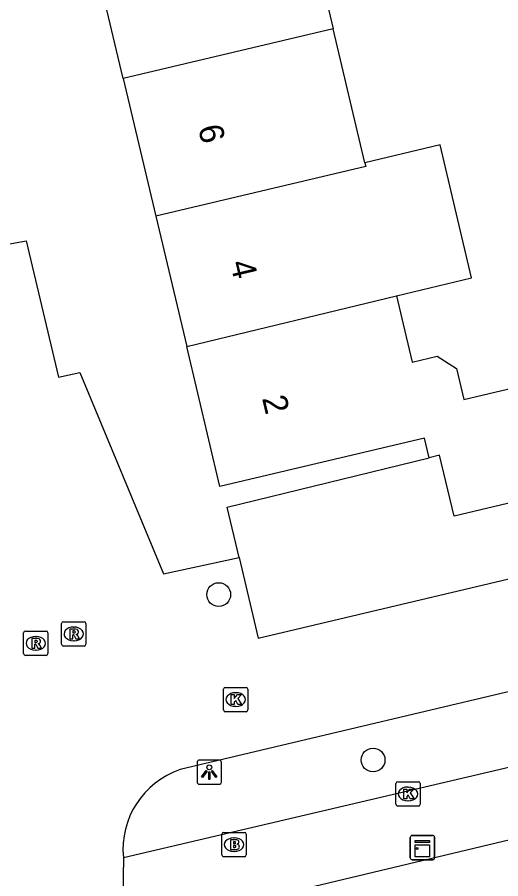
# Model space of a CAD drawing. Extents: x 158038 to 159242, y 380133 to 381214.
# Drawn here: x 158523.03 to 158542.9, y 381056.48 to 381091.9 of the extents above; entities that cross this region are included whole.
import ezdxf

# ---------------------------------------------------------------- set-up
doc = ezdxf.new("R2010")
doc.units = 0
for name, color, linetype in [('IMGEO_Boom', 7, 'Continuous'), ('IMGEO_Brandkraan', 7, 'Continuous'), ('IMGEO_Kast', 7, 'Continuous'), ('IMGEO_Kolk', 7, 'Continuous'), ('IMGEO_Lichtpunt', 7, 'Continuous'), ('IMGEO_Pand', 7, 'Continuous'), ('IMGEO_Pand_nummerreeks', 7, 'Continuous'), ('IMGEO_Parkeervlak_open', 7, 'Continuous'), ('IMGEO_Rioolput', 7, 'Continuous'), ('IMGEO_Voetpad_open', 7, 'Continuous')]:
    doc.layers.add(name, color=color, linetype=linetype)

msp = doc.modelspace()

# ---------------------------------------------------------------- linework, layer by layer
at = {"layer": 'IMGEO_Boom'}
for centre in [(158531.311, 381068.166), (158537.652, 381061.367)]:
    msp.add_circle(centre, 0.489, dxfattribs=at)
at = {"layer": 'IMGEO_Brandkraan'}
for p, q in [((158531.442, 381057.464), (158531.442, 381058.316)), ((158531.517, 381058.39), (158532.369, 381058.39)), ((158532.443, 381058.316), (158532.443, 381057.464)), ((158531.93, 381058.17), (158531.955, 381058.17)), ((158531.953, 381057.61), (158531.928, 381057.61)), ((158532.369, 381057.39), (158531.517, 381057.39))]:
    msp.add_line(p, q, dxfattribs=at)
for points in [[(158531.442, 381057.464), (158531.442, 381058.316)], [(158531.517, 381058.39), (158532.369, 381058.39)], [(158532.443, 381058.316), (158532.443, 381057.464)], [(158531.79, 381058.09), (158531.79, 381057.69), (158532.003, 381057.69)], [(158532.021, 381058.09), (158531.79, 381058.09)], [(158531.969, 381058.009), (158531.915, 381058.009), (158531.915, 381057.933)], [(158531.915, 381057.933), (158531.968, 381057.933)], [(158531.977, 381057.857), (158531.915, 381057.857), (158531.915, 381057.776)], [(158531.915, 381057.776), (158531.977, 381057.776)], [(158532.369, 381057.39), (158531.517, 381057.39)]]:
    msp.add_lwpolyline(points, dxfattribs=at)
for centre, radius, start, end in [((158531.519, 381058.314), 0.0765, 91.552, 178.448), ((158531.519, 381058.314), 0.0765, 91.552, 178.448), ((158532.367, 381058.314), 0.0765, 1.552, 88.448), ((158532.367, 381058.314), 0.0765, 1.552, 88.448), ((158531.97, 381057.971), 0.0379, 267.8285, 90.9355), ((158532.025, 381057.945), 0.145, 59.4692, 91.5367), ((158532.05, 381057.992), 0.0922, 285.5137, 58.1501), ((158532.055, 381057.8), 0.105, 301.3115, 78.989), ((158531.978, 381057.816), 0.0404, 269.8759, 90.5077), ((158532.009, 381057.941), 0.251, 268.6676, 293.5347), ((158531.519, 381057.466), 0.0765, 181.552, 268.448), ((158531.519, 381057.466), 0.0765, 181.552, 268.448), ((158532.367, 381057.466), 0.0765, 271.552, 358.448), ((158532.367, 381057.466), 0.0765, 271.552, 358.448)]:
    msp.add_arc(centre, radius, start, end, dxfattribs=at)
for centre, major_axis, ratio, start_param, end_param in [((158531.929, 381057.89), (-0.387, 0.002), 0.722429, 4.712389, 7.853982), ((158531.954, 381057.89), (-0.39, 0.002), 0.717154, 1.570796, 4.712389)]:
    msp.add_ellipse(centre, major_axis=major_axis, ratio=ratio, start_param=start_param, end_param=end_param, dxfattribs=at)
at = {"layer": 'IMGEO_Kast'}
for p, q in [((158539.257, 381058.267), (158540.098, 381058.267)), ((158540.098, 381058.267), (158539.257, 381058.267)), ((158539.182, 381057.342), (158539.182, 381058.183)), ((158539.182, 381058.183), (158539.182, 381057.342)), ((158540.182, 381058.192), (158540.182, 381057.351)), ((158540.182, 381057.351), (158540.182, 381058.192)), ((158540.107, 381057.267), (158539.266, 381057.267)), ((158539.266, 381057.267), (158540.107, 381057.267))]:
    msp.add_line(p, q, dxfattribs=at)
for points in [[(158539.377, 381058.057), (158539.977, 381058.057), (158539.977, 381057.972), (158539.377, 381057.972), (158539.377, 381058.057)], [(158539.377, 381057.882), (158539.977, 381057.882), (158539.977, 381057.393), (158539.377, 381057.393), (158539.377, 381057.882)]]:
    msp.add_lwpolyline(points, dxfattribs=at)
msp.add_circle((158539.461, 381057.731), 0.0377, dxfattribs=at)
for centre, start, end in [((158539.26, 381058.189), 92.4484, 184.2845), ((158539.26, 381058.189), 92.4484, 184.2845), ((158540.104, 381058.189), 2.4484, 94.2845), ((158540.104, 381058.189), 2.4484, 94.2845), ((158539.26, 381057.345), 182.4484, 274.2845), ((158539.26, 381057.345), 182.4484, 274.2845), ((158540.104, 381057.345), 272.4484, 4.2845), ((158540.104, 381057.345), 272.4484, 4.2845)]:
    msp.add_arc(centre, 0.0779, start, end, dxfattribs=at)
at = {"layer": 'IMGEO_Kolk'}
for p, q in [((158531.508, 381063.427), (158531.508, 381064.279)), ((158531.583, 381064.353), (158532.435, 381064.353)), ((158532.509, 381064.279), (158532.509, 381063.427)), ((158531.996, 381064.133), (158532.021, 381064.133)), ((158532.019, 381063.573), (158531.994, 381063.573)), ((158532.435, 381063.353), (158531.583, 381063.353)), ((158538.59, 381059.548), (158538.59, 381060.4)), ((158538.665, 381060.474), (158539.517, 381060.474)), ((158539.591, 381060.4), (158539.591, 381059.548)), ((158539.078, 381060.254), (158539.103, 381060.254)), ((158539.101, 381059.694), (158539.076, 381059.694)), ((158539.517, 381059.474), (158538.665, 381059.474))]:
    msp.add_line(p, q, dxfattribs=at)
for points in [[(158531.508, 381063.427), (158531.508, 381064.279)], [(158531.583, 381064.353), (158532.435, 381064.353)], [(158532.509, 381064.279), (158532.509, 381063.427)], [(158531.829, 381064.053), (158531.952, 381064.053), (158531.952, 381063.902), (158532.082, 381064.053), (158532.246, 381064.053), (158532.1, 381063.902), (158532.253, 381063.653), (158532.101, 381063.653), (158532.016, 381063.817), (158531.952, 381063.75), (158531.952, 381063.653), (158531.829, 381063.653), (158531.829, 381064.053)], [(158532.435, 381063.353), (158531.583, 381063.353)], [(158538.59, 381059.548), (158538.59, 381060.4)], [(158538.665, 381060.474), (158539.517, 381060.474)], [(158539.591, 381060.4), (158539.591, 381059.548)], [(158538.911, 381060.174), (158539.034, 381060.174), (158539.034, 381060.023), (158539.164, 381060.174), (158539.328, 381060.174), (158539.182, 381060.023), (158539.335, 381059.774), (158539.183, 381059.774), (158539.098, 381059.938), (158539.034, 381059.871), (158539.034, 381059.774), (158538.911, 381059.774), (158538.911, 381060.174)], [(158539.517, 381059.474), (158538.665, 381059.474)]]:
    msp.add_lwpolyline(points, dxfattribs=at)
for centre, start, end in [((158531.585, 381064.277), 91.552, 178.448), ((158531.585, 381064.277), 91.552, 178.448), ((158532.433, 381064.277), 1.552, 88.448), ((158532.433, 381064.277), 1.552, 88.448), ((158531.585, 381063.429), 181.552, 268.448), ((158531.585, 381063.429), 181.552, 268.448), ((158532.433, 381063.429), 271.552, 358.448), ((158532.433, 381063.429), 271.552, 358.448), ((158538.667, 381060.398), 91.552, 178.448), ((158538.667, 381060.398), 91.552, 178.448), ((158539.515, 381060.398), 1.552, 88.448), ((158539.515, 381060.398), 1.552, 88.448), ((158538.667, 381059.55), 181.552, 268.448), ((158538.667, 381059.55), 181.552, 268.448), ((158539.515, 381059.55), 271.552, 358.448), ((158539.515, 381059.55), 271.552, 358.448)]:
    msp.add_arc(centre, 0.0765, start, end, dxfattribs=at)
for centre, major_axis, ratio, start_param, end_param in [((158531.995, 381063.853), (-0.387, 0.002), 0.722429, 4.712389, 7.853982), ((158532.02, 381063.853), (-0.39, 0.002), 0.717154, 1.570796, 4.712389), ((158539.077, 381059.974), (-0.387, 0.002), 0.722429, 4.712389, 7.853982), ((158539.102, 381059.974), (-0.39, 0.002), 0.717154, 1.570796, 4.712389)]:
    msp.add_ellipse(centre, major_axis=major_axis, ratio=ratio, start_param=start_param, end_param=end_param, dxfattribs=at)
at = {"layer": 'IMGEO_Lichtpunt'}
for p, q in [((158530.424, 381061.269), (158530.424, 381060.462)), ((158530.424, 381061.269), (158530.424, 381060.462)), ((158531.326, 381061.364), (158530.518, 381061.364)), ((158531.326, 381061.364), (158530.518, 381061.364)), ((158531.42, 381060.462), (158531.42, 381061.269)), ((158531.42, 381060.462), (158531.42, 381061.269)), ((158530.518, 381060.368), (158531.326, 381060.368)), ((158530.518, 381060.368), (158531.326, 381060.368))]:
    msp.add_line(p, q, dxfattribs=at)
for points in [[(158530.798, 381060.933), (158530.837, 381060.905), (158530.649, 381060.643), (158530.611, 381060.67), (158530.798, 381060.933)], [(158530.9, 381060.885), (158530.947, 381060.885), (158530.947, 381060.563), (158530.9, 381060.563), (158530.9, 381060.885)], [(158531.01, 381060.905), (158531.048, 381060.932), (158531.235, 381060.67), (158531.196, 381060.642), (158531.01, 381060.905)]]:
    msp.add_lwpolyline(points, dxfattribs=at)
msp.add_circle((158530.923, 381061.067), 0.0994, dxfattribs=at)
for centre, start, end in [((158530.518, 381061.269), 90, 180), ((158530.518, 381061.269), 90, 180), ((158531.326, 381061.269), 0, 90), ((158531.326, 381061.269), 0, 90), ((158530.518, 381060.462), 180, 270), ((158530.518, 381060.462), 180, 270), ((158531.326, 381060.462), 270, 0), ((158531.326, 381060.462), 270, 360)]:
    msp.add_arc(centre, 0.0946, start, end, dxfattribs=at)
at = {"layer": 'IMGEO_Pand'}
for points in [[(158531.205, 381096.425), (158534.64, 381097.237), (158536.016, 381091.421)], [(158527.39, 381089.381), (158526.446, 381093.375), (158526.093, 381094.866), (158526.045, 381095.067)], [(158536.016, 381091.421), (158527.39, 381089.381)], [(158537.317, 381085.919), (158536.016, 381091.421)], [(158527.39, 381089.381), (158528.73, 381083.718)], [(158538.612, 381080.445), (158541.698, 381081.191), (158540.406, 381086.65), (158537.317, 381085.919)], [(158537.317, 381085.919), (158537.355, 381085.758), (158528.73, 381083.718)], [(158528.73, 381083.718), (158529.997, 381078.361)], [(158529.997, 381078.361), (158538.612, 381080.445)], [(158538.612, 381080.445), (158538.831, 381079.518), (158539.256, 381077.722), (158540.282, 381077.965), (158541.081, 381077.455), (158541.379, 381076.189), (158546.537, 381077.409), (158547.771, 381076.622), (158548.507, 381073.507), (158548.76, 381073.566), (158548.833, 381073.254)], [(158539.958, 381073.794), (158539.766, 381074.601), (158531.357, 381072.612), (158529.997, 381078.361)], [(158548.833, 381073.254), (158540.979, 381071.396), (158540.387, 381073.896), (158539.958, 381073.794)]]:
    msp.add_lwpolyline(points, dxfattribs=at)
at = {"layer": 'IMGEO_Parkeervlak_open'}
msp.add_lwpolyline([(158532.148, 381069.695), (158531.659, 381071.763), (158539.958, 381073.794)], dxfattribs=at)
at = {"layer": 'IMGEO_Rioolput'}
for p, q in [((158524.856, 381066.126), (158524.856, 381066.978)), ((158524.931, 381067.052), (158525.783, 381067.052)), ((158525.344, 381066.832), (158525.369, 381066.832)), ((158525.857, 381066.978), (158525.857, 381066.126)), ((158523.295, 381065.739), (158523.295, 381066.591)), ((158523.37, 381066.665), (158524.222, 381066.665)), ((158523.783, 381066.445), (158523.808, 381066.445)), ((158524.296, 381066.591), (158524.296, 381065.739)), ((158525.783, 381066.052), (158524.931, 381066.052)), ((158525.367, 381066.272), (158525.342, 381066.272)), ((158524.222, 381065.665), (158523.37, 381065.665)), ((158523.806, 381065.885), (158523.781, 381065.885))]:
    msp.add_line(p, q, dxfattribs=at)
for points in [[(158524.856, 381066.126), (158524.856, 381066.978)], [(158524.931, 381067.052), (158525.783, 381067.052)], [(158525.445, 381066.75), (158525.193, 381066.752), (158525.193, 381066.352)], [(158525.857, 381066.978), (158525.857, 381066.126)], [(158523.295, 381065.739), (158523.295, 381066.591)], [(158523.37, 381066.665), (158524.222, 381066.665)], [(158524.296, 381066.591), (158524.296, 381065.739)], [(158525.193, 381066.352), (158525.317, 381066.352), (158525.317, 381066.514), (158525.328, 381066.514)], [(158525.371, 381066.671), (158525.317, 381066.671), (158525.317, 381066.59)], [(158525.317, 381066.59), (158525.369, 381066.59)], [(158525.375, 381066.485), (158525.446, 381066.352), (158525.586, 381066.352), (158525.521, 381066.478)], [(158523.884, 381066.363), (158523.632, 381066.365), (158523.632, 381065.965)], [(158523.632, 381065.965), (158523.756, 381065.965), (158523.756, 381066.127), (158523.767, 381066.127)], [(158523.81, 381066.284), (158523.756, 381066.284), (158523.756, 381066.203)], [(158523.756, 381066.203), (158523.808, 381066.203)], [(158523.814, 381066.098), (158523.885, 381065.965), (158524.025, 381065.965), (158523.96, 381066.091)], [(158525.783, 381066.052), (158524.931, 381066.052)], [(158524.222, 381065.665), (158523.37, 381065.665)]]:
    msp.add_lwpolyline(points, dxfattribs=at)
for centre, radius, start, end in [((158524.933, 381066.976), 0.0765, 91.552, 178.448), ((158524.933, 381066.976), 0.0765, 91.552, 178.448), ((158525.444, 381066.64), 0.109, 350.3612, 89.416), ((158525.781, 381066.976), 0.0765, 1.552, 88.448), ((158525.781, 381066.976), 0.0765, 1.552, 88.448), ((158523.372, 381066.589), 0.0765, 91.552, 178.448), ((158523.372, 381066.589), 0.0765, 91.552, 178.448), ((158524.22, 381066.589), 0.0765, 1.552, 88.448), ((158524.22, 381066.589), 0.0765, 1.552, 88.448), ((158525.327, 381066.461), 0.0533, 26.0293, 88.6989), ((158525.353, 381066.779), 0.19, 274.7715, 282.9687), ((158525.377, 381066.575), 0.0964, 77.0061, 93.1865), ((158525.391, 381066.632), 0.0378, 276.6634, 79.6772), ((158525.442, 381066.64), 0.112, 277.5842, 350.9817), ((158525.426, 381066.425), 0.108, 29.5134, 73.7905), ((158523.766, 381066.074), 0.0533, 26.0293, 88.6989), ((158523.792, 381066.392), 0.19, 274.7715, 282.9687), ((158523.816, 381066.188), 0.0964, 77.0061, 93.1865), ((158523.83, 381066.245), 0.0378, 276.6634, 79.6772), ((158523.883, 381066.253), 0.109, 350.3612, 89.416), ((158523.881, 381066.253), 0.112, 277.5842, 350.9817), ((158523.865, 381066.038), 0.108, 29.5134, 73.7905), ((158524.933, 381066.128), 0.0765, 181.552, 268.448), ((158524.933, 381066.128), 0.0765, 181.552, 268.448), ((158525.781, 381066.128), 0.0765, 271.552, 358.448), ((158525.781, 381066.128), 0.0765, 271.552, 358.448), ((158523.372, 381065.741), 0.0765, 181.552, 268.448), ((158523.372, 381065.741), 0.0765, 181.552, 268.448), ((158524.22, 381065.741), 0.0765, 271.552, 358.448), ((158524.22, 381065.741), 0.0765, 271.552, 358.448)]:
    msp.add_arc(centre, radius, start, end, dxfattribs=at)
for centre, major_axis, ratio, start_param, end_param in [((158525.343, 381066.552), (-0.387, 0.002), 0.722429, 4.712389, 7.853982), ((158525.368, 381066.552), (-0.39, 0.002), 0.717154, 1.570796, 4.712389), ((158523.782, 381066.165), (-0.387, 0.002), 0.722429, 4.712389, 7.853982), ((158523.807, 381066.165), (-0.39, 0.002), 0.717154, 1.570796, 4.712389)]:
    msp.add_ellipse(centre, major_axis=major_axis, ratio=ratio, start_param=start_param, end_param=end_param, dxfattribs=at)
at = {"layer": 'IMGEO_Voetpad_open'}
for points in [[(158503.237, 381123.834), (158503.277, 381123.844), (158507.752, 381113.932), (158508.633, 381114.152), (158510.661, 381109.122), (158511.544, 381109.339), (158514.302, 381098.229), (158516.781, 381092.662), (158518.989, 381093.169), (158520.3, 381087.72), (158522.585, 381082.557), (158523.407, 381082.715), (158524.726, 381077.104), (158525.608, 381077.301), (158529.048, 381069.021), (158532.148, 381069.695)], [(158532.148, 381069.695), (158532.932, 381066.38), (158551.155, 381070.689), (158552.912, 381071.104), (158553.026, 381071.131), (158552.337, 381074.045)], [(158550.535, 381063.021), (158549.866, 381065.739), (158529.728, 381060.971)], [(158527.394, 381057.361), (158550.589, 381062.801), (158550.535, 381063.021)], [(158551.04, 381059.938), (158530.193, 381054.964), (158534.525, 381036.6), (158530.488, 381030.118)], [(158527.394, 381057.361), (158527.348, 381054.168)]]:
    msp.add_lwpolyline(points, dxfattribs=at)
msp.add_arc((158530.844, 381057.69), 3.466, 108.7886, 185.4431, dxfattribs=at)

# ---------------------------------------------------------------- texts
at = {"layer": 'IMGEO_Pand_nummerreeks'}
for s, rotation, p in [('6', 283.3096, (158530.456, 381087.368)), ('4', 283.3096, (158531.772, 381081.805)), ('2', 283.3082, (158533.088, 381076.243))]:
    msp.add_text(s, height=1, rotation=rotation, dxfattribs=at).set_placement(p)

doc.saveas('drawing.dxf')
